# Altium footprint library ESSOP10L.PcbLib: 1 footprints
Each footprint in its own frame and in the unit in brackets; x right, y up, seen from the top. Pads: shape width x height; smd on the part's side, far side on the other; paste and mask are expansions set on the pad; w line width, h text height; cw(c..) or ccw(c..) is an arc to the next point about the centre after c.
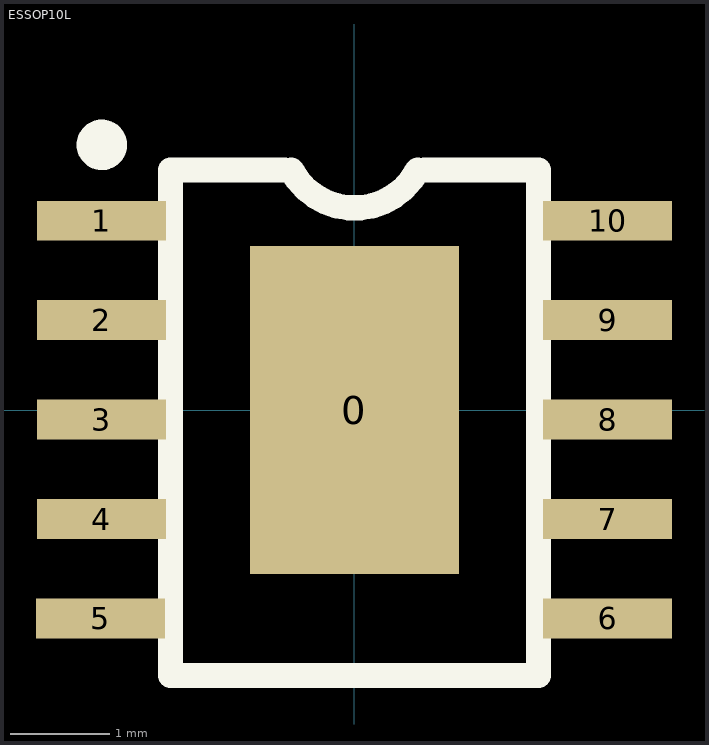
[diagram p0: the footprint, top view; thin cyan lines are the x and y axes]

## ESSOP10L [mm]
pads (11):
  rect 2.1x3.3 smd: 0(0,0)
  rect 1.3x0.4 smd: 1(-2.544,1.905) 2(-2.544,0.905) 3(-2.544,-0.095) 4(-2.544,-1.095) 5(-2.554,-2.095) 6(2.544,-2.095) 7(2.544,-1.095) 8(2.544,-0.095) 9(2.544,0.905) 10(2.544,1.905)
Top Overlay:
  circle w0.254: c-2.54,2.667 r0.127
  lines w0.254: -0.7,2.413 -1.85,2.413 -1.85,-2.667 1.85,-2.667 1.85,2.413 0.7,2.413 ; -0.635,2.413 ccw(c0,2.752) 0.635,2.413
